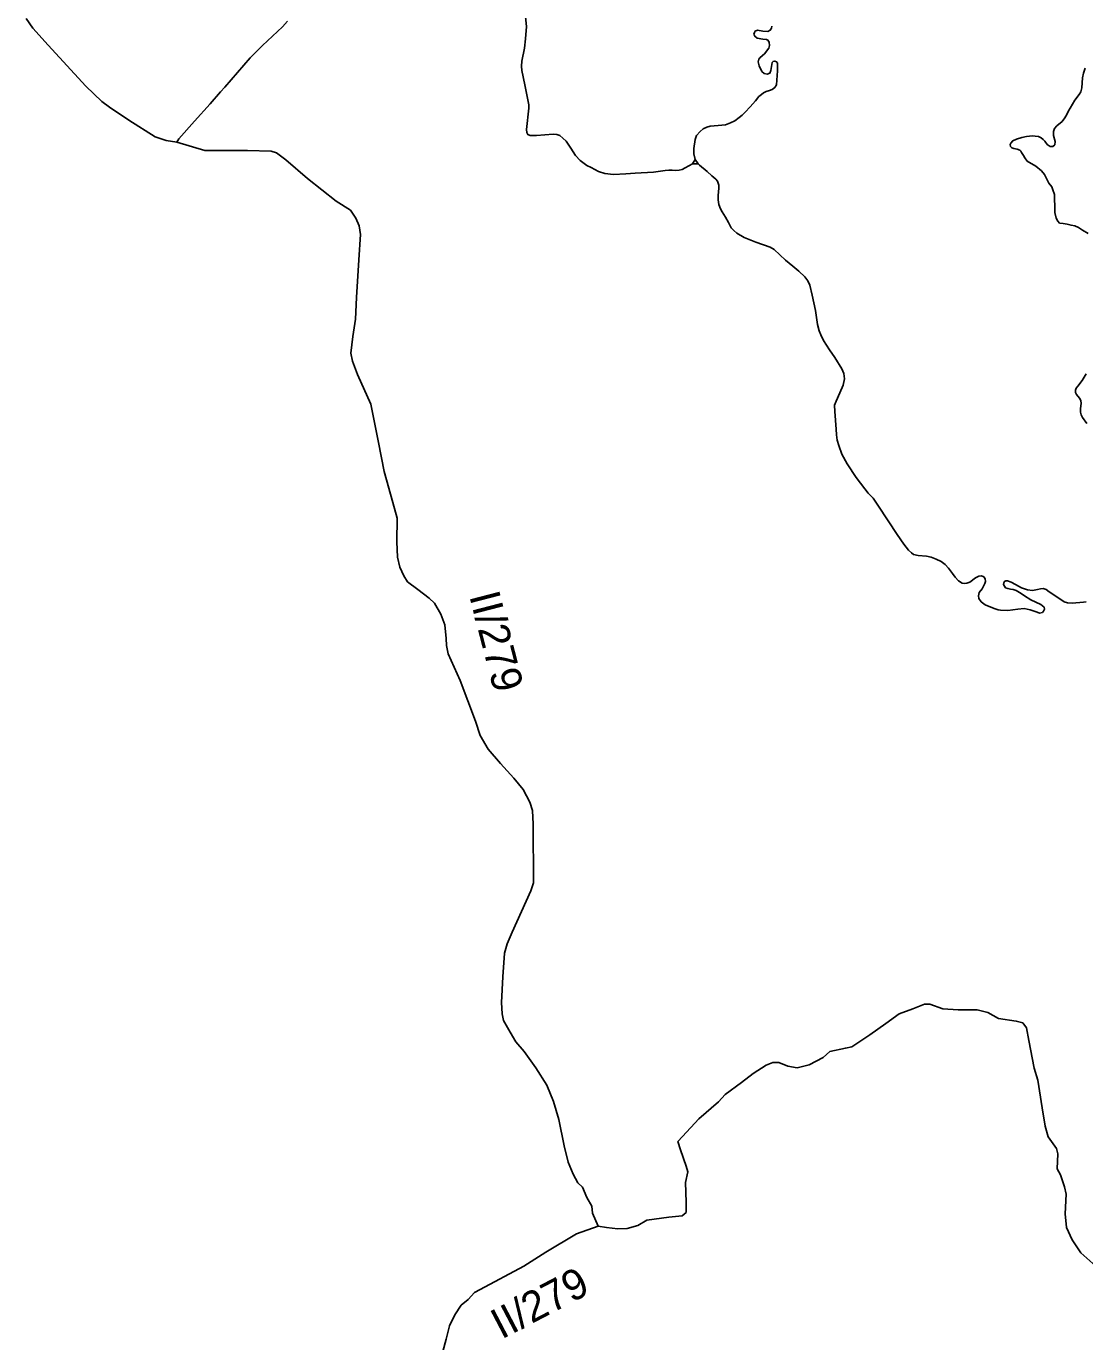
# Model space of a CAD drawing. Extents: x -789162 to -606354, y -1062736 to -945481.
# Drawn here: x -690112 to -684895, y -1004905 to -998419 of the extents above; entities that cross this region are included whole.
import ezdxf

# ---------------------------------------------------------------- set-up
doc = ezdxf.new("R2010")
doc.units = 0
for name, color, linetype in [('_SIRSI VZTAHY_SILNICE I a II TRIDY_STAV POPIS', 7, 'Continuous'), ('_SIRSI VZTAHY_SILNICE II TRIDY_STAV', 7, 'Continuous'), ('_SIRSI VZTAHY_SILNICE III TRIDY_STAV', 7, 'Continuous')]:
    doc.layers.add(name, color=color, linetype=linetype)

msp = doc.modelspace()

# ---------------------------------------------------------------- linework, layer by layer
at = {"layer": '_SIRSI VZTAHY_SILNICE II TRIDY_STAV'}
for points in [[(-690111.7, -998381.4), (-690080.2, -998427.7), (-690004.3, -998512.9), (-689819.1, -998714.8), (-689739.4, -998790.7), (-689702.4, -998818.5), (-689606.1, -998881.5), (-689476.5, -998964.8), (-689422.7, -998981.5), (-689369.5, -998990.7)], [(-689369.5, -998990.7), (-689232, -999031.5), (-689020.8, -999031.5), (-688904.2, -999035.2), (-688878.2, -999042.6), (-688831.9, -999077.8), (-688726.4, -999170.4), (-688583.7, -999281.5), (-688514.1, -999325.5), (-688487.4, -999364.9), (-688470.8, -999403.8), (-688465.2, -999446.4), (-688472.6, -999570.4), (-688483.7, -999755.7), (-688489.3, -999863.1), (-688502.3, -999948.3), (-688511.5, -1000031.6), (-688504.1, -1000070.5), (-688480, -1000135.3), (-688413.4, -1000281.6), (-688376.3, -1000470.6), (-688348.5, -1000615), (-688305.9, -1000766.9), (-688283.7, -1000844.7), (-688285.6, -1000961.4), (-688281.9, -1001037.3), (-688270.7, -1001085.4), (-688250.4, -1001128), (-688233.7, -1001157.7), (-688181.8, -1001196.6), (-688126.3, -1001239.2), (-688100.4, -1001263.3), (-688068.9, -1001317), (-688048.5, -1001370.7), (-688042.9, -1001437.3), (-688041.1, -1001472.5), (-688031.8, -1001513.3), (-687972.6, -1001644.8), (-687898.5, -1001844.8), (-687874.4, -1001915.2), (-687835.5, -1001983.7), (-687774.4, -1002054.1), (-687709.6, -1002126.3), (-687663.3, -1002181.9), (-687629.9, -1002244.9), (-687617, -1002285.6), (-687613.3, -1002352.3), (-687611.4, -1002643.1), (-687624.4, -1002681.9), (-687717, -1002885.7), (-687741, -1002943.1), (-687754, -1002989.4), (-687763.3, -1003106.1), (-687768.8, -1003232), (-687767, -1003287.6), (-687759.6, -1003320.9), (-687726.2, -1003378.3), (-687698.4, -1003426.5), (-687657.7, -1003474.6), (-687600.3, -1003554.3), (-687546.6, -1003639.5), (-687513.2, -1003721), (-687487.3, -1003809.9), (-687461.4, -1003939.5), (-687441, -1004019.2), (-687416.9, -1004078.4), (-687392.9, -1004121), (-687370.6, -1004143.2), (-687348.4, -1004193.3), (-687324.3, -1004235.8), (-687320.6, -1004271), (-687292.8, -1004335.9)], [(-687292.8, -1004335.9), (-687400.3, -1004372.9), (-687550.3, -1004463.7), (-687659.6, -1004532.2), (-687874.4, -1004647), (-687902.2, -1004661.8), (-687933.7, -1004697), (-687968.9, -1004724.8), (-688000.3, -1004773), (-688026.3, -1004826.7), (-688042.9, -1004891.5), (-688081.8, -1005037.8)]]:
    msp.add_lwpolyline(points, dxfattribs=at)
at = {"layer": '_SIRSI VZTAHY_SILNICE III TRIDY_STAV'}
for points in [[(-688823.9, -998394.5), (-688848.6, -998422), (-688948, -998513.4), (-689007.6, -998574.8), (-689133.9, -998719.1), (-689154, -998741.7), (-689206.3, -998802.1), (-689282.6, -998887.3), (-689359.9, -998973.9), (-689369.5, -998990.7)], [(-687651.3, -998372.8), (-687647, -998420), (-687651.3, -998481.4), (-687656.7, -998527.3), (-687669.2, -998590.5), (-687671.1, -998615.6), (-687668.6, -998637.9), (-687655.3, -998707.1), (-687635.6, -998807.2), (-687634.4, -998823.5), (-687647.1, -998927.3), (-687645.2, -998943.6), (-687639.8, -998953.3), (-687628.4, -998958.1), (-687618.6, -998958.2), (-687596.3, -998957), (-687514.7, -998951.9), (-687496.3, -998953.1), (-687481.7, -998957.9), (-687467.3, -998970), (-687451.1, -998985.5), (-687427.3, -999019.6), (-687404.7, -999055.7), (-687381.3, -999081.1), (-687349.8, -999104.8), (-687328.1, -999115.5), (-687309.8, -999126.1), (-687291.7, -999135.7), (-687260.3, -999144.3), (-687217.1, -999149.9), (-687157.4, -999147.3), (-687111, -999143.2), (-687020.9, -999138.6), (-686962.8, -999129.8), (-686945.1, -999128), (-686927.7, -999128.5), (-686910.5, -999130.8), (-686894.1, -999129.4), (-686879.6, -999125.5), (-686864.7, -999117), (-686828.9, -999096.8)], [(-686815.5, -999075.8), (-686821.8, -999048.5), (-686821.7, -999021.1), (-686815.4, -998977.1), (-686807.7, -998957.8), (-686790.6, -998938.7), (-686774.8, -998924.2), (-686757.9, -998915.9), (-686741.8, -998912.1), (-686701.5, -998908.3), (-686665.6, -998904.5), (-686641.2, -998895.5), (-686620, -998884.9), (-686598.7, -998869), (-686583.9, -998857.5), (-686568.6, -998843.2), (-686544, -998816.9), (-686517.6, -998786.4), (-686500.5, -998765.5), (-686488.4, -998755.3), (-686478.3, -998746.7), (-686464.9, -998740.7), (-686448.7, -998736), (-686435.9, -998730.8), (-686423, -998721.4), (-686414.9, -998708.3), (-686409.9, -998638.2), (-686408.5, -998614), (-686408.6, -998601.2), (-686413.5, -998593.7), (-686422.4, -998590.8), (-686431, -998592.7), (-686435.7, -998597.8), (-686437.3, -998607.4), (-686441.7, -998636.4), (-686446.8, -998649.9), (-686460.2, -998655), (-686475.7, -998651.8), (-686486.8, -998641.6), (-686500.4, -998614.5), (-686504.9, -998595.2), (-686501.4, -998581.8), (-686495.2, -998573.6), (-686472.9, -998554.6), (-686451.5, -998527.8), (-686448, -998514.4), (-686450.3, -998497.1), (-686456.6, -998487.4), (-686463.9, -998484.1), (-686481.4, -998483.1), (-686509.4, -998477.8), (-686521.4, -998468.3), (-686525.3, -998458.1), (-686523, -998449.2), (-686518.7, -998442.7), (-686507.5, -998438.4), (-686481.1, -998442.6), (-686457.3, -998444.1), (-686445.2, -998438.7), (-686438.6, -998428.9), (-686437.9, -998417.8)], [(-684893, -998626.2), (-684901.5, -998650.4), (-684905.4, -998673.9), (-684908.7, -998722.2), (-684914.4, -998741.9), (-684922.1, -998755.2), (-684943.6, -998784.1), (-684966.7, -998822.9), (-684974.3, -998835.7), (-684983.3, -998854), (-684993.5, -998871.1), (-685005.9, -998888.1), (-685032.2, -998910.8), (-685044, -998923.8), (-685048.4, -998938.7), (-685048.1, -998958.1), (-685041.4, -998986.7), (-685042.4, -999002.9), (-685052.2, -999011.8), (-685065.6, -999012.4), (-685079.9, -999002.2), (-685091.6, -998986.4), (-685099.2, -998977.8), (-685109.1, -998969.5), (-685123, -998961.8), (-685139.7, -998960.2), (-685151.8, -998959.2), (-685181.2, -998962.4), (-685204.9, -998968.3), (-685230.7, -998975.9), (-685249.7, -998984.5), (-685259.9, -998995.6), (-685262.7, -999001.9), (-685261.1, -999011.2), (-685253.9, -999017.8), (-685243.6, -999021.8), (-685227.8, -999025.6), (-685214.8, -999030.2), (-685209.4, -999035), (-685205.9, -999041.6), (-685197.3, -999056.9), (-685190.5, -999067.9), (-685178, -999083.8), (-685135.7, -999109.2), (-685108.4, -999132.4), (-685093.2, -999149.9), (-685071.7, -999192.8), (-685057.9, -999211.5), (-685051.7, -999224.8), (-685044.5, -999248.3), (-685043.3, -999274.9), (-685041.5, -999303.3), (-685042.1, -999337.7), (-685036.4, -999364.5), (-685028.1, -999379.4), (-685018.6, -999389.3), (-685001.1, -999391.8), (-684981.7, -999395.3), (-684962.4, -999399.8), (-684944.3, -999403.6), (-684925.5, -999411.8), (-684905.9, -999423.6), (-684877.3, -999441)], [(-686828.9, -999096.8), (-686815.5, -999075.8)], [(-686800.5, -999098.1), (-686815.5, -999075.8)], [(-686800.5, -999098.1), (-686828.9, -999096.8)], [(-684887.6, -1001256.6), (-684900.6, -1001258.3), (-684957.6, -1001263.2), (-684979.9, -1001262), (-684996.2, -1001257.1), (-685031.8, -1001231.8), (-685070.9, -1001207.1), (-685085.2, -1001196.1), (-685099.2, -1001191.9), (-685113.2, -1001193.1), (-685127, -1001195.9), (-685152, -1001200.2), (-685176.7, -1001198), (-685206.5, -1001187.4), (-685236.4, -1001171.9), (-685256.9, -1001160.6), (-685275.6, -1001153.9), (-685283.4, -1001153.6), (-685290.9, -1001157.2), (-685293.8, -1001163.4), (-685294.5, -1001171.3), (-685290.9, -1001179.9), (-685284.9, -1001187.1), (-685274.4, -1001191.4), (-685261.4, -1001194.2), (-685247.7, -1001196), (-685232.6, -1001200.9), (-685207.9, -1001215.2), (-685192.3, -1001227.4), (-685160.6, -1001246.3), (-685112.1, -1001270.6), (-685095.1, -1001283.2), (-685093.3, -1001293.7), (-685097.8, -1001302.6), (-685103.9, -1001310.2), (-685117.3, -1001312.5), (-685130.1, -1001308), (-685163.4, -1001295.8), (-685194.2, -1001290.3), (-685224.2, -1001293.2), (-685274.4, -1001298.9), (-685309.8, -1001298.4), (-685322.4, -1001296.8), (-685340.6, -1001289.8), (-685385.1, -1001271.8), (-685405.3, -1001256.5), (-685417.5, -1001240.4), (-685419.1, -1001227.4), (-685414.7, -1001210.9), (-685401.1, -1001192), (-685388, -1001166.7), (-685383.9, -1001156.3), (-685386.4, -1001142.9), (-685392.7, -1001133.1), (-685404.2, -1001128.3), (-685416.9, -1001129.6), (-685432.6, -1001138.6), (-685462, -1001159.8), (-685475.5, -1001165), (-685486.2, -1001166.6), (-685498.4, -1001164.9), (-685517.1, -1001152.6), (-685534, -1001134.7), (-685547.4, -1001117.5), (-685566.4, -1001091.5), (-685582.6, -1001072.1), (-685602.8, -1001057.8), (-685627.1, -1001047), (-685652.5, -1001036.9), (-685674.7, -1001032.4), (-685715.4, -1001029.2), (-685738.4, -1001023.9), (-685748, -1001015.2), (-685762.9, -1001001.6), (-685775.7, -1000987.7), (-685786.1, -1000972.4), (-685819.1, -1000924.2), (-685911.5, -1000785.4), (-685938.2, -1000745.1), (-685962.7, -1000721.9), (-685979.6, -1000699.7), (-686021.8, -1000644.2), (-686066.5, -1000575.9), (-686091.9, -1000529.5), (-686107.1, -1000485.4), (-686114.4, -1000460.6), (-686118.6, -1000434.1), (-686120.8, -1000405.4), (-686126.4, -1000318.8), (-686128.9, -1000287.4), (-686120.9, -1000266.9), (-686101.7, -1000226.5), (-686085.4, -1000188.5), (-686078.2, -1000157.4), (-686082.4, -1000130.5), (-686092.2, -1000107.9), (-686126.8, -1000052.3), (-686153.5, -1000013.9), (-686183, -999968.5), (-686195.7, -999940.9), (-686203.3, -999920.6), (-686211.6, -999888.8), (-686222.6, -999820.6), (-686238.1, -999745), (-686250, -999695.8), (-686260.2, -999674.5), (-686274.9, -999653.8), (-686303.7, -999626.2), (-686333.2, -999601.8), (-686370, -999571.9), (-686425.9, -999520.5), (-686446.2, -999508.1), (-686515.4, -999483), (-686573.2, -999459.9), (-686610, -999439.5), (-686624.6, -999426.8), (-686637, -999412.2), (-686650, -999386.5), (-686665.9, -999359.8), (-686682.4, -999334.1), (-686690.4, -999318.6), (-686697.7, -999297.9), (-686702.3, -999275.4), (-686702.1, -999253.8), (-686698.9, -999217), (-686697.7, -999202.1), (-686704.3, -999183), (-686713.5, -999172.2), (-686732.8, -999156.1), (-686755.8, -999135.7), (-686793.9, -999103.8), (-686800.5, -999098.1)], [(-684888.4, -1000132.6), (-684907.4, -1000165.3), (-684928.7, -1000193.5), (-684936.7, -1000203.4), (-684940.5, -1000213.5), (-684941.1, -1000224.6), (-684936.3, -1000234.8), (-684920.5, -1000252.6), (-684914.4, -1000264.6), (-684912.6, -1000278.2), (-684915.5, -1000304.2), (-684915.1, -1000321.5), (-684912.2, -1000334.5), (-684905.2, -1000348.1), (-684884.6, -1000378.3)], [(-684840.8, -1004532.2), (-684914.9, -1004466.6), (-684957.2, -1004403.1), (-684984.8, -1004341.7), (-684991.1, -1004274), (-684986.9, -1004176.6), (-684995.3, -1004140.6), (-685014.4, -1004081.4), (-685031.3, -1004051.7), (-685027.1, -1003977.7), (-685033.4, -1003952.3), (-685075.8, -1003895.1), (-685090.6, -1003842.2), (-685105.4, -1003751.2), (-685126.6, -1003615.7), (-685143.5, -1003556.4), (-685171, -1003418.9), (-685181.6, -1003357.5), (-685200.7, -1003332.1), (-685232.4, -1003323.6), (-685319.2, -1003310.9), (-685372.1, -1003281.3), (-685425, -1003268.6), (-685518.2, -1003268.6), (-685594.4, -1003264.3), (-685657.9, -1003241.1), (-685685.4, -1003241.1), (-685742.5, -1003264.3), (-685810.3, -1003287.6), (-685875.9, -1003336.3), (-685954.2, -1003391.3), (-686043.1, -1003450.6), (-686074.8, -1003457), (-686151, -1003473.9), (-686184.9, -1003503.5), (-686252.6, -1003539.5), (-686311.9, -1003554.3), (-686358.5, -1003545.9), (-686402.9, -1003528.9), (-686432.6, -1003528.9), (-686464.3, -1003541.6), (-686529.9, -1003581.8), (-686587.1, -1003626.3), (-686667.5, -1003685.6), (-686699.3, -1003721.5), (-686796.6, -1003806.2), (-686877.1, -1003893), (-686900.3, -1003918.4), (-686887.6, -1003958.6), (-686860.1, -1004039), (-686851.7, -1004066.6), (-686862.2, -1004119.5), (-686860.1, -1004216.8), (-686860.1, -1004267.6), (-686879.2, -1004284.6), (-686944.8, -1004290.9), (-687052.7, -1004305.7), (-687097.2, -1004331.1), (-687150.1, -1004346), (-687196.7, -1004348.1), (-687251.7, -1004341.7), (-687292.8, -1004335.9)]]:
    msp.add_lwpolyline(points, dxfattribs=at)

# ---------------------------------------------------------------- texts
at = {"layer": '_SIRSI VZTAHY_SILNICE I a II TRIDY_STAV POPIS'}
for rotation, p in [(284.5196, (-687929.3, -1001226.6)), (27.62886, (-687769.7, -1004895.1))]:
    msp.add_text('II/279', height=150, rotation=rotation, dxfattribs=at).set_placement(p)

doc.saveas('drawing.dxf')
